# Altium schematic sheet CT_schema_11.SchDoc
size 278 x 170 mm
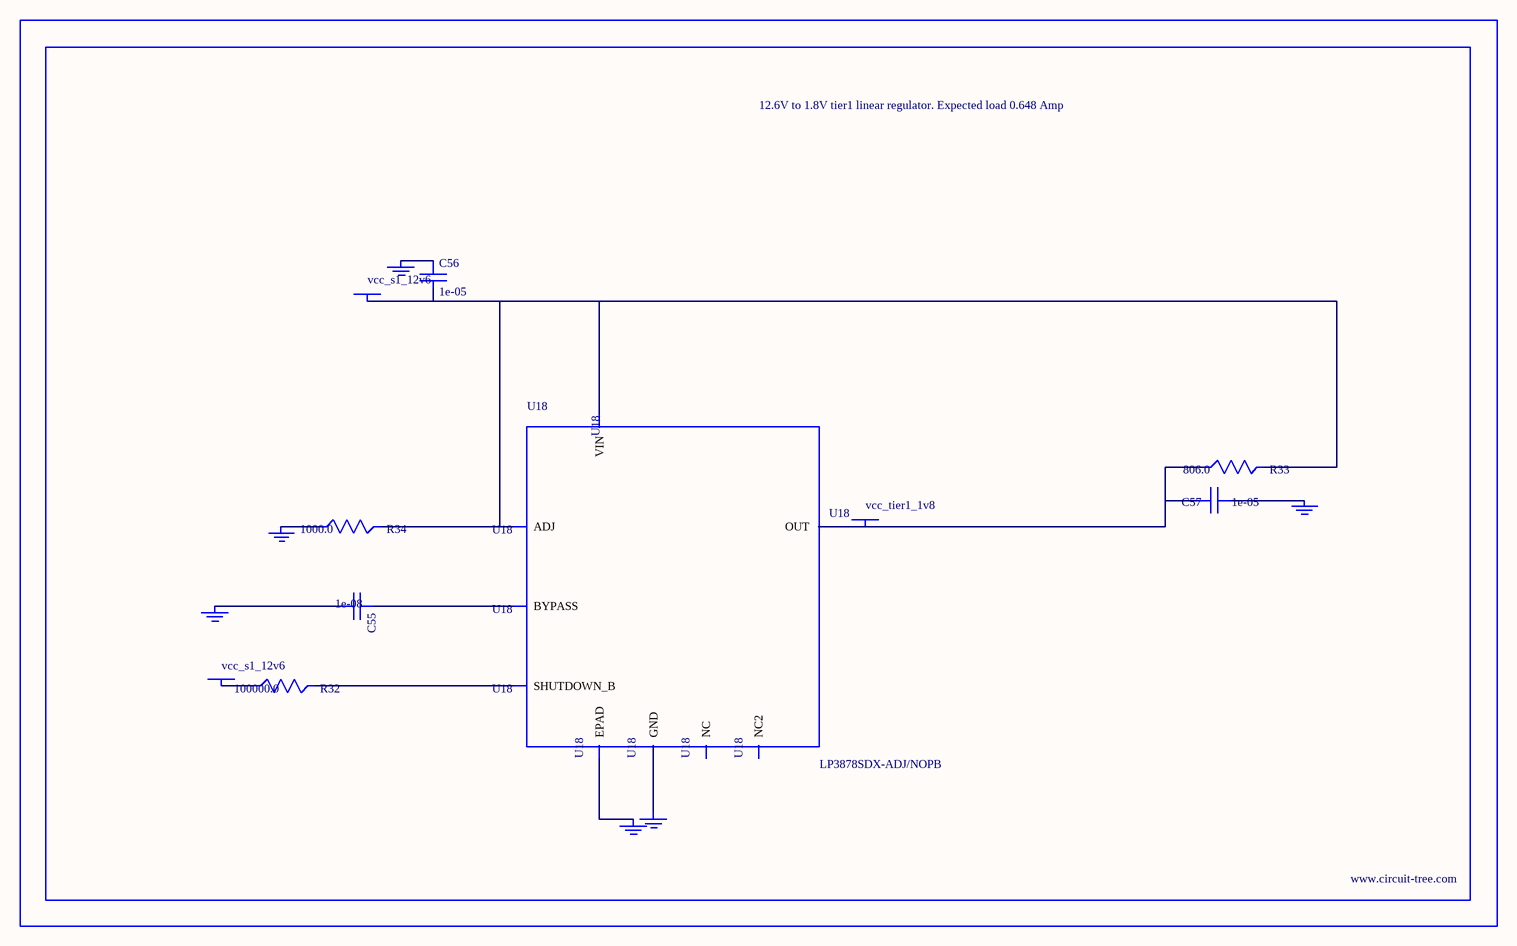
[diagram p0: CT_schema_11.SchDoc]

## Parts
BORDER10  (no value)
C55  1e-08  [C0402]
C56  1e-05  [C1210]
C57  1e-05  [C0805]
GND_INSTANCE_10_0  (no value)
GND_INSTANCE_10_1  (no value)
GND_INSTANCE_10_2  (no value)
GND_INSTANCE_10_3  (no value)
GND_INSTANCE_10_4  (no value)
GND_INSTANCE_10_5  (no value)
POWER_INSTANCE_10_0  vcc_s1_12v6
POWER_INSTANCE_10_1  vcc_s1_12v6
POWER_INSTANCE_10_2  vcc_tier1_1v8
R32  100000.0  [R0603]
R33  806.0  [R0603]
R34  1000.0  [R0603]
U18  LP3878SDX-ADJ/NOPB  [WSON-8]

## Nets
NetC55_1: C55.1 U18.1(BYPASS)
NetC55_2: C55.2 GND_INSTANCE_10_0.0(GND)
NetC56_1: C56.1 GND_INSTANCE_10_1.0(GND)
NetC56_2: C56.2 POWER_INSTANCE_10_0.0(PWR) R33.2 R34.2 U18.4(VIN) U18.6(ADJ)
NetC57_1: C57.1 GND_INSTANCE_10_2.0(GND)
NetC57_2: C57.2 POWER_INSTANCE_10_2.0(PWR) R33.1 U18.5(OUT)
NetGND_INSTANCE_10_3_0: GND_INSTANCE_10_3.0(GND) R34.1
NetGND_INSTANCE_10_4_0: GND_INSTANCE_10_4.0(GND) U18.PAD(EPAD)
NetGND_INSTANCE_10_5_0: GND_INSTANCE_10_5.0(GND) U18.3(GND)
NetPOWER_INSTANCE_10_1_0: POWER_INSTANCE_10_1.0(PWR) R32.1
NetR32_2: R32.2 U18.8(SHUTDOWN_B)

Not connected (* = marked no-connect by the designer): U18 2(NC) 7(NC2)

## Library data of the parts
BORDER10 = BORDER_PAGE10
C55 = C0402C103K3RAC
C56 = C1210C106K5PACTU
C57 = GRM219R60J106ME19D
GND_INSTANCE_10_0-GND_INSTANCE_10_5 = GND
POWER_INSTANCE_10_0-POWER_INSTANCE_10_2 = PWR
R32 = RC0603JR-07100KL
R33 = ERJ-3EKF8060V
R34 = RC0603JR-071KL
